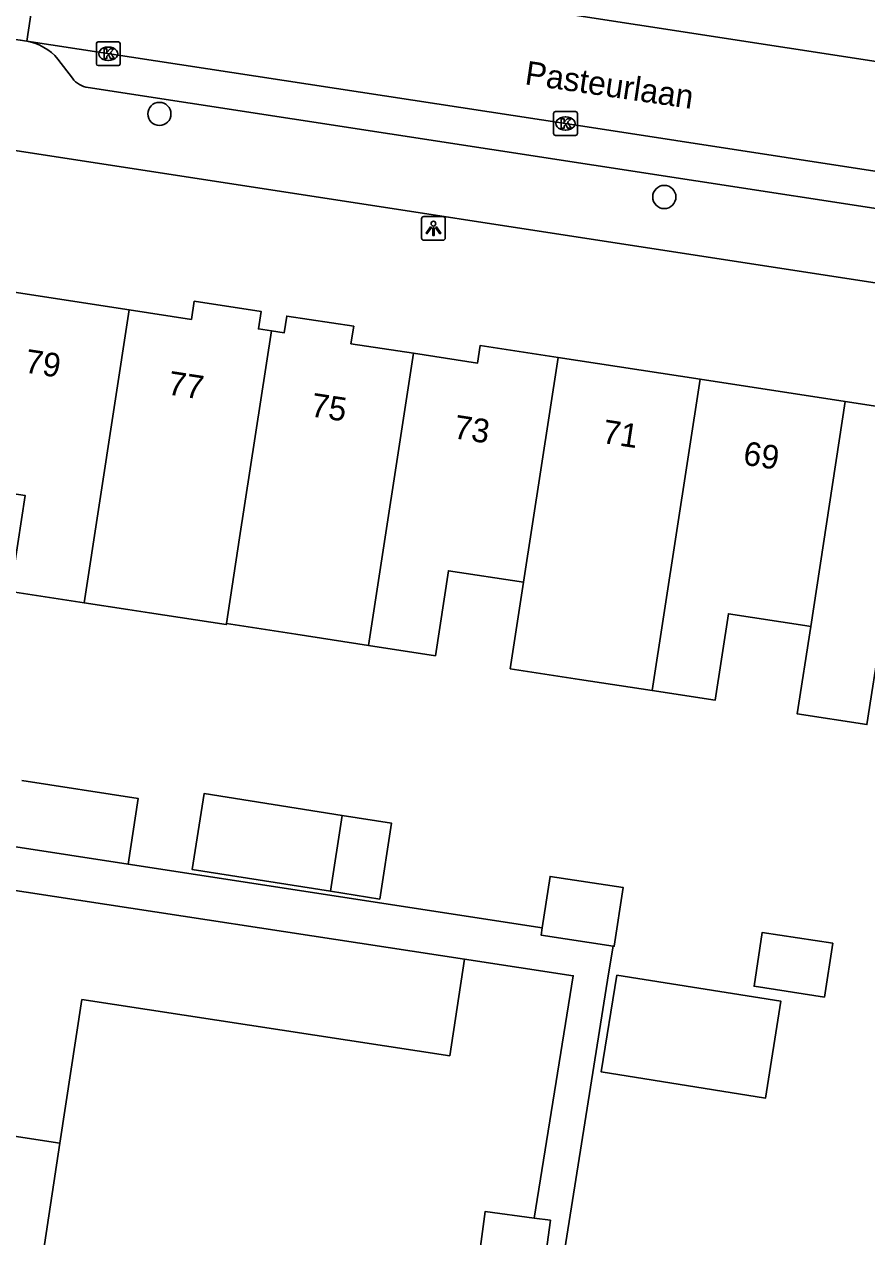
# Model space of a CAD drawing. Extents: x 161486 to 162249, y 379484 to 380829.
# Drawn here: x 161849.1 to 161884.6, y 380504.4 to 380555.5 of the extents above; entities that cross this region are included whole.
import ezdxf

# ---------------------------------------------------------------- set-up
doc = ezdxf.new("R2010")
doc.units = 0
for name, color, linetype in [('IMGEO_Boom', 7, 'Continuous'), ('IMGEO_Kolk', 7, 'Continuous'), ('IMGEO_Lichtpunt', 7, 'Continuous'), ('IMGEO_Openbare_ruimte_label', 7, 'Continuous'), ('IMGEO_Pand', 7, 'Continuous'), ('IMGEO_Pand_nummerreeks', 7, 'Continuous'), ('IMGEO_Rijbaan_lokaal_open', 7, 'Continuous'), ('IMGEO_Voetpad_open', 7, 'Continuous')]:
    doc.layers.add(name, color=color, linetype=linetype)

msp = doc.modelspace()

# ---------------------------------------------------------------- linework, layer by layer
at = {"layer": 'IMGEO_Boom'}
for centre in [(161854.747, 380551.721), (161876.021, 380548.223)]:
    msp.add_circle(centre, 0.489, dxfattribs=at)
at = {"layer": 'IMGEO_Kolk'}
for p, q in [((161852.092, 380553.833), (161852.092, 380554.685)), ((161852.167, 380554.759), (161853.019, 380554.759)), ((161852.58, 380554.539), (161852.605, 380554.539)), ((161853.093, 380554.685), (161853.093, 380553.833)), ((161852.603, 380553.979), (161852.578, 380553.979)), ((161853.019, 380553.759), (161852.167, 380553.759)), ((161871.357, 380550.893), (161871.357, 380551.745)), ((161871.432, 380551.819), (161872.284, 380551.819)), ((161872.358, 380551.745), (161872.358, 380550.893)), ((161871.845, 380551.599), (161871.87, 380551.599)), ((161872.284, 380550.819), (161871.432, 380550.819)), ((161871.868, 380551.039), (161871.843, 380551.039))]:
    msp.add_line(p, q, dxfattribs=at)
for points in [[(161852.092, 380553.833), (161852.092, 380554.685)], [(161852.167, 380554.759), (161853.019, 380554.759)], [(161852.413, 380554.459), (161852.536, 380554.459), (161852.536, 380554.308), (161852.666, 380554.459), (161852.83, 380554.459), (161852.684, 380554.308), (161852.837, 380554.059), (161852.685, 380554.059), (161852.6, 380554.223), (161852.536, 380554.156), (161852.536, 380554.059), (161852.413, 380554.059), (161852.413, 380554.459)], [(161853.093, 380554.685), (161853.093, 380553.833)], [(161853.019, 380553.759), (161852.167, 380553.759)], [(161871.357, 380550.893), (161871.357, 380551.745)], [(161871.432, 380551.819), (161872.284, 380551.819)], [(161872.358, 380551.745), (161872.358, 380550.893)], [(161871.678, 380551.519), (161871.801, 380551.519), (161871.801, 380551.368), (161871.931, 380551.519), (161872.095, 380551.519), (161871.949, 380551.368), (161872.102, 380551.119), (161871.95, 380551.119), (161871.865, 380551.283), (161871.801, 380551.216), (161871.801, 380551.119), (161871.678, 380551.119), (161871.678, 380551.519)], [(161872.284, 380550.819), (161871.432, 380550.819)]]:
    msp.add_lwpolyline(points, dxfattribs=at)
for centre, start, end in [((161852.169, 380554.683), 91.552, 178.448), ((161852.169, 380554.683), 91.552, 178.448), ((161853.017, 380554.683), 1.552, 88.448), ((161853.017, 380554.683), 1.552, 88.448), ((161852.169, 380553.835), 181.552, 268.448), ((161852.169, 380553.835), 181.552, 268.448), ((161853.017, 380553.835), 271.552, 358.448), ((161853.017, 380553.835), 271.552, 358.448), ((161871.434, 380551.743), 91.552, 178.448), ((161871.434, 380551.743), 91.552, 178.448), ((161872.282, 380551.743), 1.552, 88.448), ((161872.282, 380551.743), 1.552, 88.448), ((161871.434, 380550.895), 181.552, 268.448), ((161871.434, 380550.895), 181.552, 268.448), ((161872.282, 380550.895), 271.552, 358.448), ((161872.282, 380550.895), 271.552, 358.448)]:
    msp.add_arc(centre, 0.0765, start, end, dxfattribs=at)
for centre, major_axis, ratio, start_param, end_param in [((161852.579, 380554.259), (-0.387, 0.002), 0.722429, 4.712389, 7.853982), ((161852.604, 380554.259), (-0.39, 0.002), 0.717154, 1.570796, 4.712389), ((161871.844, 380551.319), (-0.387, 0.002), 0.722429, 4.712389, 7.853982), ((161871.869, 380551.319), (-0.39, 0.002), 0.717154, 1.570796, 4.712389)]:
    msp.add_ellipse(centre, major_axis=major_axis, ratio=ratio, start_param=start_param, end_param=end_param, dxfattribs=at)
at = {"layer": 'IMGEO_Lichtpunt'}
for p, q in [((161865.796, 380547.301), (161865.796, 380546.494)), ((161865.796, 380547.301), (161865.796, 380546.494)), ((161866.698, 380547.396), (161865.89, 380547.396)), ((161866.698, 380547.396), (161865.89, 380547.396)), ((161866.792, 380546.494), (161866.792, 380547.301)), ((161866.792, 380546.494), (161866.792, 380547.301)), ((161865.89, 380546.4), (161866.698, 380546.4)), ((161865.89, 380546.4), (161866.698, 380546.4))]:
    msp.add_line(p, q, dxfattribs=at)
for points in [[(161866.17, 380546.965), (161866.209, 380546.937), (161866.021, 380546.675), (161865.983, 380546.702), (161866.17, 380546.965)], [(161866.272, 380546.917), (161866.319, 380546.917), (161866.319, 380546.595), (161866.272, 380546.595), (161866.272, 380546.917)], [(161866.382, 380546.937), (161866.42, 380546.964), (161866.607, 380546.702), (161866.568, 380546.674), (161866.382, 380546.937)]]:
    msp.add_lwpolyline(points, dxfattribs=at)
msp.add_circle((161866.295, 380547.099), 0.0994, dxfattribs=at)
for centre, start, end in [((161865.89, 380547.301), 90, 180), ((161865.89, 380547.301), 90, 180), ((161866.698, 380547.301), 0, 90), ((161866.698, 380547.301), 0, 90), ((161865.89, 380546.494), 180, 270), ((161865.89, 380546.494), 180, 270), ((161866.698, 380546.494), 270, 0), ((161866.698, 380546.494), 270, 360)]:
    msp.add_arc(centre, 0.0946, start, end, dxfattribs=at)
at = {"layer": 'IMGEO_Pand'}
for points in [[(161851.58, 380531.125), (161848.478, 380531.601), (161849.098, 380535.638), (161846, 380536.114), (161846.165, 380537.188), (161845.449, 380537.298), (161845.882, 380540.115), (161846.657, 380539.996), (161847.336, 380544.413), (161853.478, 380543.469)], [(161853.478, 380543.469), (161856.099, 380543.066), (161856.217, 380543.832), (161859.03, 380543.4), (161858.917, 380542.667), (161859.468, 380542.582)], [(161851.58, 380531.125), (161853.478, 380543.469)], [(161859.468, 380542.582), (161860.006, 380542.5), (161860.115, 380543.206), (161862.933, 380542.773), (161862.82, 380542.039), (161865.448, 380541.635)], [(161857.571, 380530.248), (161858.127, 380533.86), (161859.468, 380542.582)], [(161865.448, 380541.635), (161863.555, 380529.327)], [(161865.448, 380541.635), (161868.148, 380541.22), (161868.263, 380541.967), (161871.548, 380541.462)], [(161871.548, 380541.462), (161870.09, 380531.986)], [(161871.548, 380541.462), (161877.533, 380540.542)], [(161875.515, 380527.423), (161877.533, 380540.542)], [(161877.533, 380540.542), (161883.646, 380539.603)], [(161882.189, 380530.131), (161883.646, 380539.603)], [(161883.646, 380539.603), (161889.692, 380538.674)], [(161870.09, 380531.986), (161866.928, 380532.472), (161866.378, 380528.893), (161863.555, 380529.327)], [(161875.515, 380527.423), (161872.452, 380527.894), (161869.53, 380528.343), (161870.09, 380531.986)], [(161857.571, 380530.248), (161857.565, 380530.203), (161854.336, 380530.701), (161853.421, 380530.842), (161851.58, 380531.125)], [(161882.189, 380530.131), (161881.94, 380530.169), (161878.724, 380530.663), (161878.163, 380527.016), (161875.515, 380527.423)], [(161863.555, 380529.327), (161860.497, 380529.798), (161857.571, 380530.248)], [(161888.236, 380529.203), (161885.124, 380529.681), (161884.557, 380525.991), (161881.622, 380526.442), (161882.189, 380530.131)], [(161848.945, 380523.631), (161853.857, 380522.876), (161853.433, 380520.116)], [(161861.962, 380518.967), (161856.122, 380519.889), (161856.627, 380523.084), (161862.454, 380522.164)], [(161862.454, 380522.164), (161864.533, 380521.835), (161864.029, 380518.641), (161861.962, 380518.967)], [(161861.962, 380518.967), (161862.454, 380522.164)], [(161853.433, 380520.116), (161848.521, 380520.871)], [(161873.861, 380516.658), (161873.909, 380516.651), (161874.289, 380519.121), (161871.212, 380519.594), (161870.88, 380517.435)], [(161848.129, 380519.087), (161867.603, 380516.11)], [(161870.88, 380517.435), (161870.832, 380517.124), (161873.861, 380516.658)], [(161882.774, 380514.513), (161883.122, 380516.776), (161880.15, 380517.233), (161879.803, 380514.97), (161882.774, 380514.513)], [(161867.603, 380516.11), (161866.981, 380512.037), (161851.479, 380514.406), (161850.555, 380508.352)], [(161874.016, 380515.436), (161880.937, 380514.336), (161880.289, 380510.255), (161873.368, 380511.355), (161874.016, 380515.436)], [(161842.389, 380509.6), (161850.555, 380508.352)], [(161850.555, 380508.352), (161849.507, 380501.483)], [(161870.308, 380501.577), (161867.994, 380501.89), (161868.48, 380505.479), (161870.532, 380505.201)], [(161870.532, 380505.201), (161871.226, 380505.107), (161870.74, 380501.518), (161870.308, 380501.577)]]:
    msp.add_lwpolyline(points, dxfattribs=at)
at = {"layer": 'IMGEO_Rijbaan_lokaal_open'}
for points in [[(161849.159, 380554.782), (161849.846, 380559.342)], [(161849.846, 380559.342), (161887.499, 380553.536), (161890.424, 380553.087)], [(161914.156, 380544.809), (161910.838, 380545.329), (161890.447, 380548.452), (161871.858, 380551.32), (161849.159, 380554.782)]]:
    msp.add_lwpolyline(points, dxfattribs=at)
msp.add_arc((161847.891, 380548.379), 6.527, 78.7972, 155.0956, dxfattribs=at)
at = {"layer": 'IMGEO_Voetpad_open'}
for points in [[(161850.473, 380554.036), (161851.08, 380553.228)], [(161851.745, 380552.829), (161911.363, 380543.674)], [(161914.351, 380539.988), (161885.9, 380544.447), (161848.674, 380550.183)], [(161870.88, 380517.435), (161853.433, 380520.116)], [(161867.068, 380471.144), (161869.458, 380487.783), (161870.006, 380491.935), (161870.395, 380494.882), (161873.671, 380515.491), (161873.861, 380516.658)], [(161867.603, 380516.11), (161872.182, 380515.41), (161870.532, 380505.201)]]:
    msp.add_lwpolyline(points, dxfattribs=at)
for centre, radius, start, end in [((161848.818, 380552.651), 2.158, 39.9227, 80.9074), ((161851.899, 380553.839), 1.021, 216.7187, 261.3538)]:
    msp.add_arc(centre, radius, start, end, dxfattribs=at)

# ---------------------------------------------------------------- texts
at = {"layer": 'IMGEO_Openbare_ruimte_label'}
msp.add_text('Pasteurlaan', height=1, rotation=351.6024, dxfattribs=at).set_placement((161870.11, 380552.975))
at = {"layer": 'IMGEO_Pand_nummerreeks'}
for s, rotation, p in [('79', 351.2754, (161849.033, 380540.833)), ('77', 351.2739, (161855.058, 380539.909)), ('75', 351.2754, (161861.082, 380538.984)), ('73', 351.2754, (161867.106, 380538.06)), ('71', 351.2624, (161873.369, 380537.863)), ('69', 351.2624, (161879.305, 380536.951))]:
    msp.add_text(s, height=1, rotation=rotation, dxfattribs=at).set_placement(p)

doc.saveas('drawing.dxf')
